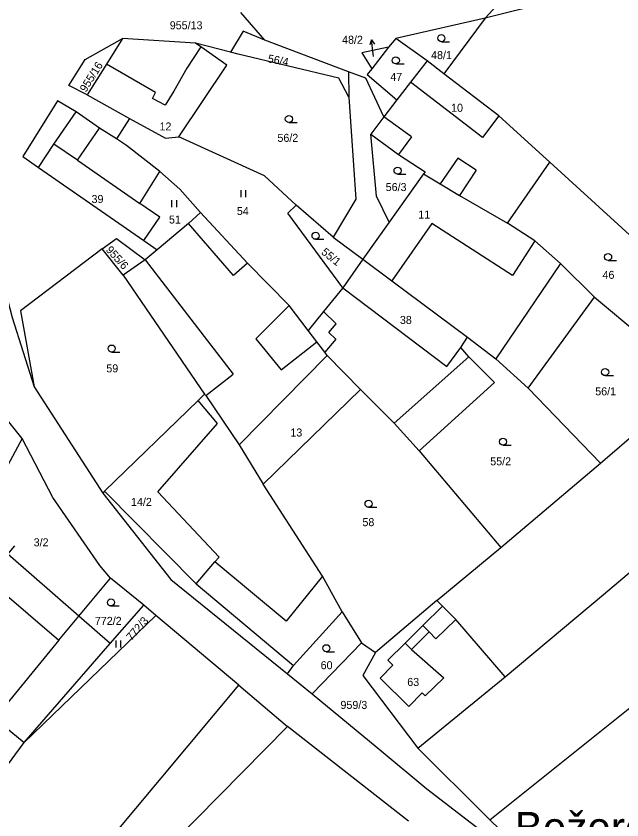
# Model space of a CAD drawing. Extents: x -751333 to -746055, y -1133395 to -1129777.
# Drawn here: x -747826.9 to -747698.2, y -1131157.3 to -1130986.6 of the extents above; entities that cross this region are included whole.
import ezdxf

# ---------------------------------------------------------------- set-up
doc = ezdxf.new("R2010")
doc.units = 0
for name, color, linetype in [('Hranice parcel', 7, 'Continuous'), ('Parcelní čísla', 7, 'Continuous'), ('Pop  PČ popisy', 7, 'Continuous'), ('Vnitřní kresba', 7, 'Continuous'), ('Značky kultur', 7, 'Continuous')]:
    doc.layers.add(name, color=color, linetype=linetype)

msp = doc.modelspace()

# ---------------------------------------------------------------- linework, layer by layer
at = {"layer": 'Hranice parcel'}
for p, q in [((-747727.26, -1130987.09), (-747723.14, -1130982.58)), ((-747774.01, -1130991.73), (-747779.16, -1130985.88)), ((-747727.26, -1130987.09), (-747746.19, -1130991.34)), ((-747727.26, -1130987.09), (-747735.98, -1130998.89)), ((-747804.24, -1130991.35), (-747807.64, -1130996.81)), ((-747788.75, -1130992.33), (-747804.24, -1130991.35)), ((-747781.36, -1130994.26), (-747788.75, -1130992.33)), ((-747756.26, -1130998.42), (-747774.01, -1130991.73)), ((-747746.19, -1130991.34), (-747747.76, -1130993.24)), ((-747739.57, -1130996.15), (-747746.19, -1130991.34)), ((-747747.76, -1130993.24), (-747751.34, -1130997.82)), ((-747807.64, -1130996.81), (-747811.81, -1131003.33)), ((-747792.29, -1131012.25), (-747782.13, -1130997.05)), ((-747739.57, -1130996.15), (-747743.1, -1131000.68)), ((-747735.98, -1130998.89), (-747739.57, -1130996.15)), ((-747756.26, -1130998.42), (-747756.19, -1131003.83)), ((-747756.19, -1131003.83), (-747758.32, -1130999.81)), ((-747743.1, -1131000.68), (-747745.97, -1131004.41)), ((-747811.81, -1131003.33), (-747815.68, -1131001.33)), ((-747811.81, -1131003.33), (-747802.79, -1131008.38)), ((-747818.08, -1131004.63), (-747825.46, -1131016.4)), ((-747745.97, -1131004.41), (-747748.76, -1131008.04)), ((-747802.79, -1131008.38), (-747805.54, -1131012.68)), ((-747748.76, -1131008.04), (-747751.5, -1131011.7)), ((-747722.47, -1131030.61), (-747713.52, -1131017.65)), ((-747713.52, -1131017.65), (-747672.07, -1131055.39)), ((-747759.51, -1131033.58), (-747767.4, -1131026.79)), ((-747799.75, -1131034.27), (-747796.93, -1131036.25)), ((-747759.51, -1131033.58), (-747753.2, -1131038.23)), ((-747804.15, -1131041.6), (-747808.56, -1131036.05)), ((-747796.93, -1131036.25), (-747799.49, -1131038.4)), ((-747799.49, -1131038.4), (-747804.15, -1131041.6)), ((-747753.2, -1131038.23), (-747757.45, -1131044.29)), ((-747804.15, -1131041.6), (-747786.82, -1131066.91)), ((-747718.1, -1131065.6), (-747704.02, -1131046.27)), ((-747704.02, -1131046.27), (-747682.65, -1131064.18)), ((-747823.07, -1131065.32), (-747808.48, -1131087.91)), ((-747702.76, -1131081.57), (-747718.1, -1131065.6)), ((-747702.76, -1131081.57), (-747682.65, -1131064.18)), ((-747774.37, -1131086), (-747753.72, -1131065.9)), ((-747825.56, -1131076.31), (-747830.09, -1131070.64)), ((-747741.27, -1131078.96), (-747723.91, -1131099.47)), ((-747723.91, -1131099.47), (-747702.76, -1131081.57)), ((-747737.5, -1131110.74), (-747723.91, -1131099.47)), ((-747813.56, -1131114.04), (-747806.82, -1131105.96)), ((-747799.76, -1131111.71), (-747806.82, -1131105.96)), ((-747806.92, -1131119.82), (-747799.76, -1131111.71)), ((-747797.21, -1131113.88), (-747799.76, -1131111.71)), ((-747737.5, -1131110.74), (-747750.5, -1131121.76)), ((-747736.31, -1131111.95), (-747737.5, -1131110.74)), ((-747757.6, -1131113.1), (-747753.47, -1131119.73)), ((-747733.44, -1131114.73), (-747736.31, -1131111.95)), ((-747825.19, -1131140.88), (-747797.21, -1131113.88)), ((-747806.92, -1131119.82), (-747813.56, -1131114.04)), ((-747779.57, -1131128.72), (-747797.21, -1131113.88)), ((-747722.98, -1131126.94), (-747733.44, -1131114.73)), ((-747825.19, -1131140.88), (-747806.92, -1131119.82)), ((-747764.01, -1131130.51), (-747753.47, -1131119.73)), ((-747753.47, -1131119.73), (-747750.5, -1131121.76)), ((-747769.24, -1131126.32), (-747764.01, -1131130.51)), ((-747741.53, -1131142.09), (-747722.98, -1131126.94)), ((-747826.65, -1131184.92), (-747779.57, -1131128.72)), ((-747779.57, -1131128.72), (-747769.22, -1131137.45)), ((-747743.52, -1131157.59), (-747769.22, -1131137.45)), ((-747705.95, -1131176.64), (-747726.24, -1131157.28))]:
    msp.add_line(p, q, dxfattribs=at)
for points in [[(-747924.97, -1130956.33), (-747918.19, -1130956.61), (-747897.81, -1130956.39), (-747883.35, -1130957.23), (-747867.68, -1130968.89), (-747853.38, -1130983.52), (-747843.2, -1130998.16), (-747832.03, -1131034.24), (-747827.69, -1131050.62), (-747823.07, -1131065.32)], [(-747641.15, -1131027.46), (-747677.24, -1130997.39), (-747699.35, -1130980.06), (-747727.26, -1130987.09)], [(-747774.01, -1130991.73), (-747778.63, -1130989.83), (-747781.36, -1130994.26)], [(-747815.68, -1131001.33), (-747812.24, -1130995.82), (-747804.24, -1130991.35)], [(-747782.13, -1130997.05), (-747787.65, -1130993.13), (-747788.75, -1130992.33)], [(-747747.76, -1130993.24), (-747753.43, -1130994.41), (-747751.34, -1130997.82)], [(-747758.32, -1130999.81), (-747779.73, -1130994.69), (-747781.36, -1130994.26)], [(-747748.76, -1131008.04), (-747752.58, -1130999.77), (-747756.26, -1130998.42)], [(-747751.34, -1130997.82), (-747752.28, -1130999), (-747745.97, -1131004.41)], [(-747713.52, -1131017.65), (-747724.31, -1131007.81), (-747735.98, -1130998.89)], [(-747756.19, -1131003.83), (-747754.69, -1131025.46), (-747759.51, -1131033.58)], [(-747805.54, -1131012.68), (-747809.15, -1131010.43), (-747814.14, -1131006.93), (-747818.08, -1131004.63)], [(-747802.79, -1131008.38), (-747795.15, -1131012.54), (-747792.29, -1131012.25)], [(-747796.37, -1131019.61), (-747803.44, -1131014.07), (-747805.54, -1131012.68)], [(-747767.4, -1131026.79), (-747774.1, -1131020.52), (-747792.29, -1131012.25)], [(-747751.5, -1131011.7), (-747745.61, -1131016), (-747739.97, -1131019.67), (-747740.32, -1131020.09)], [(-747740.32, -1131020.09), (-747747.65, -1131030.39), (-747750.3, -1131024.84), (-747751.5, -1131011.7)], [(-747825.46, -1131016.4), (-747822.1, -1131018.76), (-747799.75, -1131034.27)], [(-747799.75, -1131034.27), (-747796.33, -1131029.3), (-747800.58, -1131026.38), (-747796.37, -1131019.61)], [(-747787.69, -1131028.33), (-747792.06, -1131023.38), (-747796.37, -1131019.61)], [(-747740.32, -1131020.09), (-747736.76, -1131022.27), (-747732.68, -1131024.74), (-747722.47, -1131030.61)], [(-747757.45, -1131044.29), (-747769.17, -1131028.48), (-747767.4, -1131026.79)], [(-747787.69, -1131028.33), (-747790.26, -1131030.63), (-747796.93, -1131036.25)], [(-747764.81, -1131053.38), (-747768.86, -1131048.06), (-747777.74, -1131039.06), (-747787.69, -1131028.33)], [(-747704.02, -1131046.27), (-747711.26, -1131039.16), (-747716.71, -1131034.32), (-747722.47, -1131030.61)], [(-747808.56, -1131036.05), (-747805.55, -1131033.82), (-747799.49, -1131038.4)], [(-747808.56, -1131036.05), (-747825.94, -1131049.2), (-747823.07, -1131065.32)], [(-747753.2, -1131038.23), (-747747.07, -1131042.82), (-747730.95, -1131054.8)], [(-747757.45, -1131044.29), (-747760.29, -1131047.82), (-747761.54, -1131049.36), (-747764.81, -1131053.38)], [(-747722.98, -1131126.94), (-747702.08, -1131109.45), (-747662.38, -1131075.87), (-747627.11, -1131046.39)], [(-747753.72, -1131065.9), (-747760.77, -1131058.7), (-747761.31, -1131057.99), (-747762.97, -1131055.8), (-747764.81, -1131053.38)], [(-747741.27, -1131078.96), (-747725.22, -1131064.42), (-747730.67, -1131058.96), (-747732.42, -1131057), (-747730.95, -1131054.8)], [(-747730.95, -1131054.8), (-747724.97, -1131059.43), (-747718.1, -1131065.6)], [(-747726.24, -1131157.28), (-747690.81, -1131128.96), (-747643.31, -1131087.92), (-747612.55, -1131063.71)], [(-747786.82, -1131066.91), (-747788.23, -1131068.27), (-747808.1, -1131087.52), (-747808.48, -1131087.91)], [(-747786.82, -1131066.91), (-747786.55, -1131067.19), (-747779.51, -1131077.69), (-747774.37, -1131086)], [(-747753.72, -1131065.9), (-747746.57, -1131073.05), (-747741.27, -1131078.96)], [(-747825.56, -1131076.31), (-747832.27, -1131088.57), (-747836.06, -1131094.48)], [(-747806.82, -1131105.96), (-747809.11, -1131103.29), (-747819.11, -1131088.84), (-747825.56, -1131076.31)], [(-747757.6, -1131113.1), (-747761.8, -1131105.54), (-747774.37, -1131086)], [(-747808.48, -1131087.91), (-747794.01, -1131106.24), (-747769.24, -1131126.32)], [(-747813.56, -1131114.04), (-747828.66, -1131100.91), (-747827.12, -1131099.14)], [(-747769.24, -1131126.32), (-747767.92, -1131124.54), (-747757.6, -1131113.1)], [(-747750.5, -1131121.76), (-747753.2, -1131126.63), (-747741.53, -1131142.09)], [(-747764.01, -1131130.51), (-747750.16, -1131141.94), (-747739.59, -1131150.73), (-747705.95, -1131176.64)], [(-747769.22, -1131137.45), (-747798.15, -1131166.84), (-747817.77, -1131191.32)], [(-747836.24, -1131155.33), (-747830.35, -1131147.8), (-747825.19, -1131140.88)], [(-747726.24, -1131157.28), (-747727.01, -1131156.54), (-747741.53, -1131142.09)]]:
    msp.add_lwpolyline(points, dxfattribs=at)
at = {"layer": 'Pop  PČ popisy'}
for p, q in [((-747751.356, -1130991.641), (-747751.731, -1130992.696)), ((-747750.99, -1130994.62), (-747751.356, -1130991.641)), ((-747751.356, -1130991.641), (-747750.737, -1130992.574)), ((-747750.92, -1130995.23), (-747750.99, -1130994.62))]:
    msp.add_line(p, q, dxfattribs=at)
at = {"layer": 'Vnitřní kresba'}
for p, q in [((-747787.65, -1130993.13), (-747790.59, -1130997.7)), ((-747797.23, -1131002.81), (-747807.64, -1130996.81)), ((-747790.59, -1130997.7), (-747793.38, -1131002.53)), ((-747727.8, -1131012.38), (-747743.1, -1131000.68)), ((-747793.38, -1131002.53), (-747795.2, -1131005.55)), ((-747797.92, -1131004.08), (-747797.23, -1131002.81)), ((-747795.2, -1131005.55), (-747797.92, -1131004.08)), ((-747818.85, -1131013.81), (-747814.14, -1131006.93)), ((-747742.91, -1131012.25), (-747748.76, -1131008.04)), ((-747724.31, -1131007.81), (-747727.8, -1131012.38)), ((-747813.84, -1131017.24), (-747809.15, -1131010.43)), ((-747742.91, -1131012.25), (-747745.61, -1131016)), ((-747822.1, -1131018.76), (-747818.85, -1131013.81)), ((-747813.84, -1131017.24), (-747818.85, -1131013.81)), ((-747813.84, -1131017.24), (-747800.58, -1131026.38)), ((-747733.04, -1131016.75), (-747736.76, -1131022.27)), ((-747729.17, -1131019.31), (-747733.04, -1131016.75)), ((-747729.17, -1131019.31), (-747732.68, -1131024.74)), ((-747780.7, -1131041.7), (-747790.26, -1131030.63)), ((-747747.65, -1131030.39), (-747753.2, -1131038.23)), ((-747738.59, -1131030.64), (-747747.07, -1131042.82)), ((-747721.43, -1131041.73), (-747738.59, -1131030.64)), ((-747716.71, -1131034.32), (-747721.43, -1131041.73)), ((-747799.49, -1131038.4), (-747780.78, -1131062.62)), ((-747777.74, -1131039.06), (-747780.7, -1131041.7)), ((-747711.26, -1131039.16), (-747724.97, -1131059.43)), ((-747757.45, -1131044.29), (-747735.34, -1131061.01)), ((-747768.86, -1131048.06), (-747775.97, -1131055.14)), ((-747758.85, -1131051.98), (-747761.54, -1131049.36)), ((-747760.42, -1131053.77), (-747758.85, -1131051.98)), ((-747758.98, -1131055.25), (-747760.42, -1131053.77)), ((-747775.97, -1131055.14), (-747770.54, -1131061.71)), ((-747758.98, -1131055.25), (-747761.31, -1131057.99)), ((-747770.54, -1131061.71), (-747762.97, -1131055.8)), ((-747735.34, -1131061.01), (-747732.42, -1131057)), ((-747760.77, -1131058.7), (-747779.51, -1131077.69)), ((-747730.67, -1131058.96), (-747746.57, -1131073.05)), ((-747786.55, -1131067.19), (-747780.78, -1131062.62)), ((-747784.12, -1131073.14), (-747788.23, -1131068.27)), ((-747796.8, -1131087.65), (-747784.12, -1131073.14)), ((-747788.64, -1131107.19), (-747808.1, -1131087.52)), ((-747783.76, -1131101.49), (-747796.8, -1131087.65)), ((-747784.63, -1131102.5), (-747783.76, -1131101.49)), ((-747788.64, -1131107.19), (-747784.63, -1131102.5)), ((-747769.52, -1131115.12), (-747784.63, -1131102.5)), ((-747833.62, -1131105.57), (-747817.82, -1131119.12)), ((-747761.8, -1131105.54), (-747769.52, -1131115.12)), ((-747788.64, -1131107.19), (-747767.92, -1131124.54)), ((-747740.46, -1131116.05), (-747736.31, -1131111.95)), ((-747817.82, -1131119.12), (-747813.56, -1131114.04)), ((-747737.72, -1131118.82), (-747733.44, -1131114.73)), ((-747744.21, -1131119.77), (-747740.46, -1131116.05)), ((-747740.46, -1131116.05), (-747739.12, -1131117.4)), ((-747739.12, -1131117.4), (-747742.88, -1131121.12)), ((-747739.12, -1131117.4), (-747737.72, -1131118.82)), ((-747817.82, -1131119.12), (-747831.4, -1131135.72)), ((-747747.9, -1131123.42), (-747744.21, -1131119.77)), ((-747744.21, -1131119.77), (-747742.88, -1131121.12)), ((-747742.88, -1131121.12), (-747736.04, -1131127.17)), ((-747746.83, -1131124.48), (-747747.9, -1131123.42)), ((-747749.52, -1131127.2), (-747746.83, -1131124.48)), ((-747743.43, -1131133.22), (-747749.52, -1131127.2)), ((-747739.95, -1131130.99), (-747736.04, -1131127.17)), ((-747743.43, -1131133.22), (-747740.6, -1131130.35)), ((-747740.6, -1131130.35), (-747739.95, -1131130.99)), ((-747831.4, -1131135.72), (-747825.19, -1131140.88))]:
    msp.add_line(p, q, dxfattribs=at)
at = {"layer": 'Značky kultur'}
for p, q in [((-747736.533, -1130992.05), (-747734.783, -1130992.05)), ((-747746.213, -1130996.77), (-747744.463, -1130996.77)), ((-747768.933, -1131009.21), (-747767.183, -1131009.21)), ((-747745.843, -1131020.19), (-747744.093, -1131020.19)), ((-747779.051, -1131025.08), (-747779.051, -1131023.58)), ((-747778.05, -1131025.08), (-747778.05, -1131023.58)), ((-747793.761, -1131027.17), (-747793.761, -1131025.67)), ((-747792.76, -1131027.17), (-747792.76, -1131025.67)), ((-747763.263, -1131034.01), (-747761.513, -1131034.01)), ((-747701.113, -1131038.52), (-747699.363, -1131038.52)), ((-747806.583, -1131057.97), (-747804.833, -1131057.97)), ((-747701.743, -1131062.96), (-747699.993, -1131062.96)), ((-747723.453, -1131077.74), (-747721.703, -1131077.74)), ((-747752.003, -1131090.92), (-747750.253, -1131090.92)), ((-747806.733, -1131111.88), (-747804.983, -1131111.88)), ((-747805.611, -1131120.7), (-747805.611, -1131119.2)), ((-747804.61, -1131120.7), (-747804.61, -1131119.2)), ((-747760.973, -1131121.6), (-747759.223, -1131121.6))]:
    msp.add_line(p, q, dxfattribs=at)
for centre in [(-747736.533, -1130991.3), (-747746.213, -1130996.02), (-747768.933, -1131008.46), (-747745.843, -1131019.44), (-747763.263, -1131033.26), (-747701.113, -1131037.77), (-747806.583, -1131057.22), (-747701.743, -1131062.21), (-747723.453, -1131076.99), (-747752.003, -1131090.17), (-747806.733, -1131111.13), (-747760.973, -1131120.85)]:
    msp.add_circle(centre, 0.75, dxfattribs=at)

# ---------------------------------------------------------------- texts
at = {"layer": 'Parcelní čísla'}
for s, p in [('955/13', (-747794.235, -1130989.418)), ('48/2', (-747757.628, -1130992.49)), ('48/1', (-747738.72, -1130995.75)), ('47', (-747747.39, -1131000.39)), ('10', (-747734.47, -1131006.93)), ('12', (-747796.42, -1131010.9)), ('56/2', (-747771.36, -1131013.32)), ('56/3', (-747748.36, -1131023.77)), ('39', (-747810.85, -1131026.31)), ('54', (-747779.98, -1131028.86)), ('11', (-747741.44, -1131029.61)), ('51', (-747794.4, -1131030.66)), ('46', (-747702.3, -1131042.41)), ('38', (-747745.34, -1131051.99)), ('59', (-747807.71, -1131062.27)), ('56/1', (-747703.85, -1131067.15)), ('13', (-747768.61, -1131075.89)), ('55/2', (-747726.15, -1131082.01)), ('14/2', (-747802.47, -1131090.63)), ('58', (-747753.3, -1131094.93)), ('3/2', (-747823.15, -1131099.21)), ('772/2', (-747810.148, -1131115.89)), ('60', (-747762.18, -1131125.31)), ('63', (-747743.78, -1131128.86)), ('959/3', (-747757.97, -1131133.74))]:
    msp.add_text(s, height=1.7, dxfattribs=at).set_placement(p)
for s, rotation, p in [('56/4', 349, (-747773.512, -1130996.404)), ('955/16', 58, (-747812.041, -1131002.908)), ('955/6', 312, (-747807.931, -1131036.358)), ('55/1', 321, (-747762.184, -1131036.99)), ('772/3', 49, (-747802.358, -1131119.387))]:
    msp.add_text(s, height=1.7, rotation=rotation, dxfattribs=at).set_placement(p)
at = {"layer": 'Pop  PČ popisy'}
msp.add_text('Bežerovice', height=6.7, dxfattribs=at).set_placement((-747720.953, -1131162.31))

doc.saveas('drawing.dxf')
